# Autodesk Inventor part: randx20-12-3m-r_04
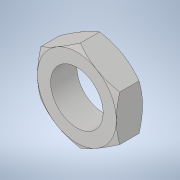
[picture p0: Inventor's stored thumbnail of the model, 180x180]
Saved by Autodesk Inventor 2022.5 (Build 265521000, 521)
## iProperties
Created: 2021-02
Part Number: randx20-12-3m-r_04
Material: 一般
Document SubType Name: Modeling
Designer: ImaoCorp
Density: 1 g/cm^3
Appearance: 既定
Author: ImaoCorp
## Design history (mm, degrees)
feature "randx20-12-3m-r_04"
node "ソリッド1"
